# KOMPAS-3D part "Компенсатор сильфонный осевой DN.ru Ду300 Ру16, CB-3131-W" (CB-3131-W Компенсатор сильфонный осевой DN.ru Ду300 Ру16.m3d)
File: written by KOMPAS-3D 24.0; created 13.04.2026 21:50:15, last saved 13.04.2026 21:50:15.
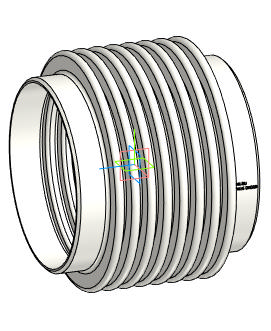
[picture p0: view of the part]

Document properties: Автор: DN.RU; Полное имя файла: D:\PROJECT CAD\DN.RU\...197(ACTUALE). CB-3131-W Компенсатор сильфонный осевой DN.ru\Исходники\DN300\CB-3131-W Компенсатор сильфонный осевой DN.ru Ду300 Ру16.m3d

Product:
- Body: Твердое тело1  | qty 1
    Масса: 33.985995
- Part/product: Компенсатор сильфонный осевой DN.ru Ду300 Ру16  | designation CB-3131-W
    Масса: 13.8
    Раздел спецификации: Прочие изделия
    Комментарий: D140-02129
    Примечание: D140-02129
    additional columns: Типовые

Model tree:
1. Твердое тело1  (labels: Твердое тело1)

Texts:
  CB-3131-W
